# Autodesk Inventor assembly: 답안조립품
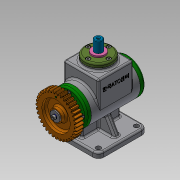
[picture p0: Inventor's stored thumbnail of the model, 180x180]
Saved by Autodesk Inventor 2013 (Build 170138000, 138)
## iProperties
Created: 2019-01
Part Number: 답안조립품
Document SubType Name: Assembly
Designer: Administrator
Author: Administrator
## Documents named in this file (18)
- C:\Documents and Settings\Administrator\바탕 화면\390107V1028\답안조립품.iam
- C:\Documents and Settings\Administrator\바탕 화면\390107V1028\본체.ipt
- C:\Documents and Settings\Administrator\바탕 화면\390107V1028\가변스프링.ipt
- C:\Documents and Settings\Administrator\바탕 화면\390107V1028\뒤커버.ipt
- C:\Documents and Settings\Administrator\바탕 화면\390107V1028\멈춤링.ipt
- C:\Documents and Settings\Administrator\바탕 화면\390107V1028\베어링 6203.ipt
- C:\Documents and Settings\Administrator\바탕 화면\390107V1028\볼트 M4.ipt
- C:\Documents and Settings\Administrator\바탕 화면\390107V1028\부시.ipt
- C:\Documents and Settings\Administrator\바탕 화면\390107V1028\상부커버.ipt
- C:\Documents and Settings\Administrator\바탕 화면\390107V1028\스퍼기어.ipt
- C:\Documents and Settings\Administrator\바탕 화면\390107V1028\스프링와셔.ipt
- C:\Documents and Settings\Administrator\바탕 화면\390107V1028\스프링조립용 와셔.ipt
- C:\Documents and Settings\Administrator\바탕 화면\390107V1028\슬라이더.ipt
- C:\Documents and Settings\Administrator\바탕 화면\390107V1028\앞커버.ipt
- C:\Documents and Settings\Administrator\바탕 화면\390107V1028\오일 실 17 30 5.ipt
- C:\Documents and Settings\Administrator\바탕 화면\390107V1028\키 4x4x12.ipt
- C:\Documents and Settings\Administrator\바탕 화면\390107V1028\편심축.ipt
- C:\Documents and Settings\Administrator\바탕 화면\390107V1028\평와셔.ipt
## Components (1 placed, 1 different names)
1. 가변스프링:1
